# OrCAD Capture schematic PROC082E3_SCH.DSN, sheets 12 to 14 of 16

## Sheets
12 16. HARDWARE SCHEMATICS: title: HARDWARE SCHEMATICS
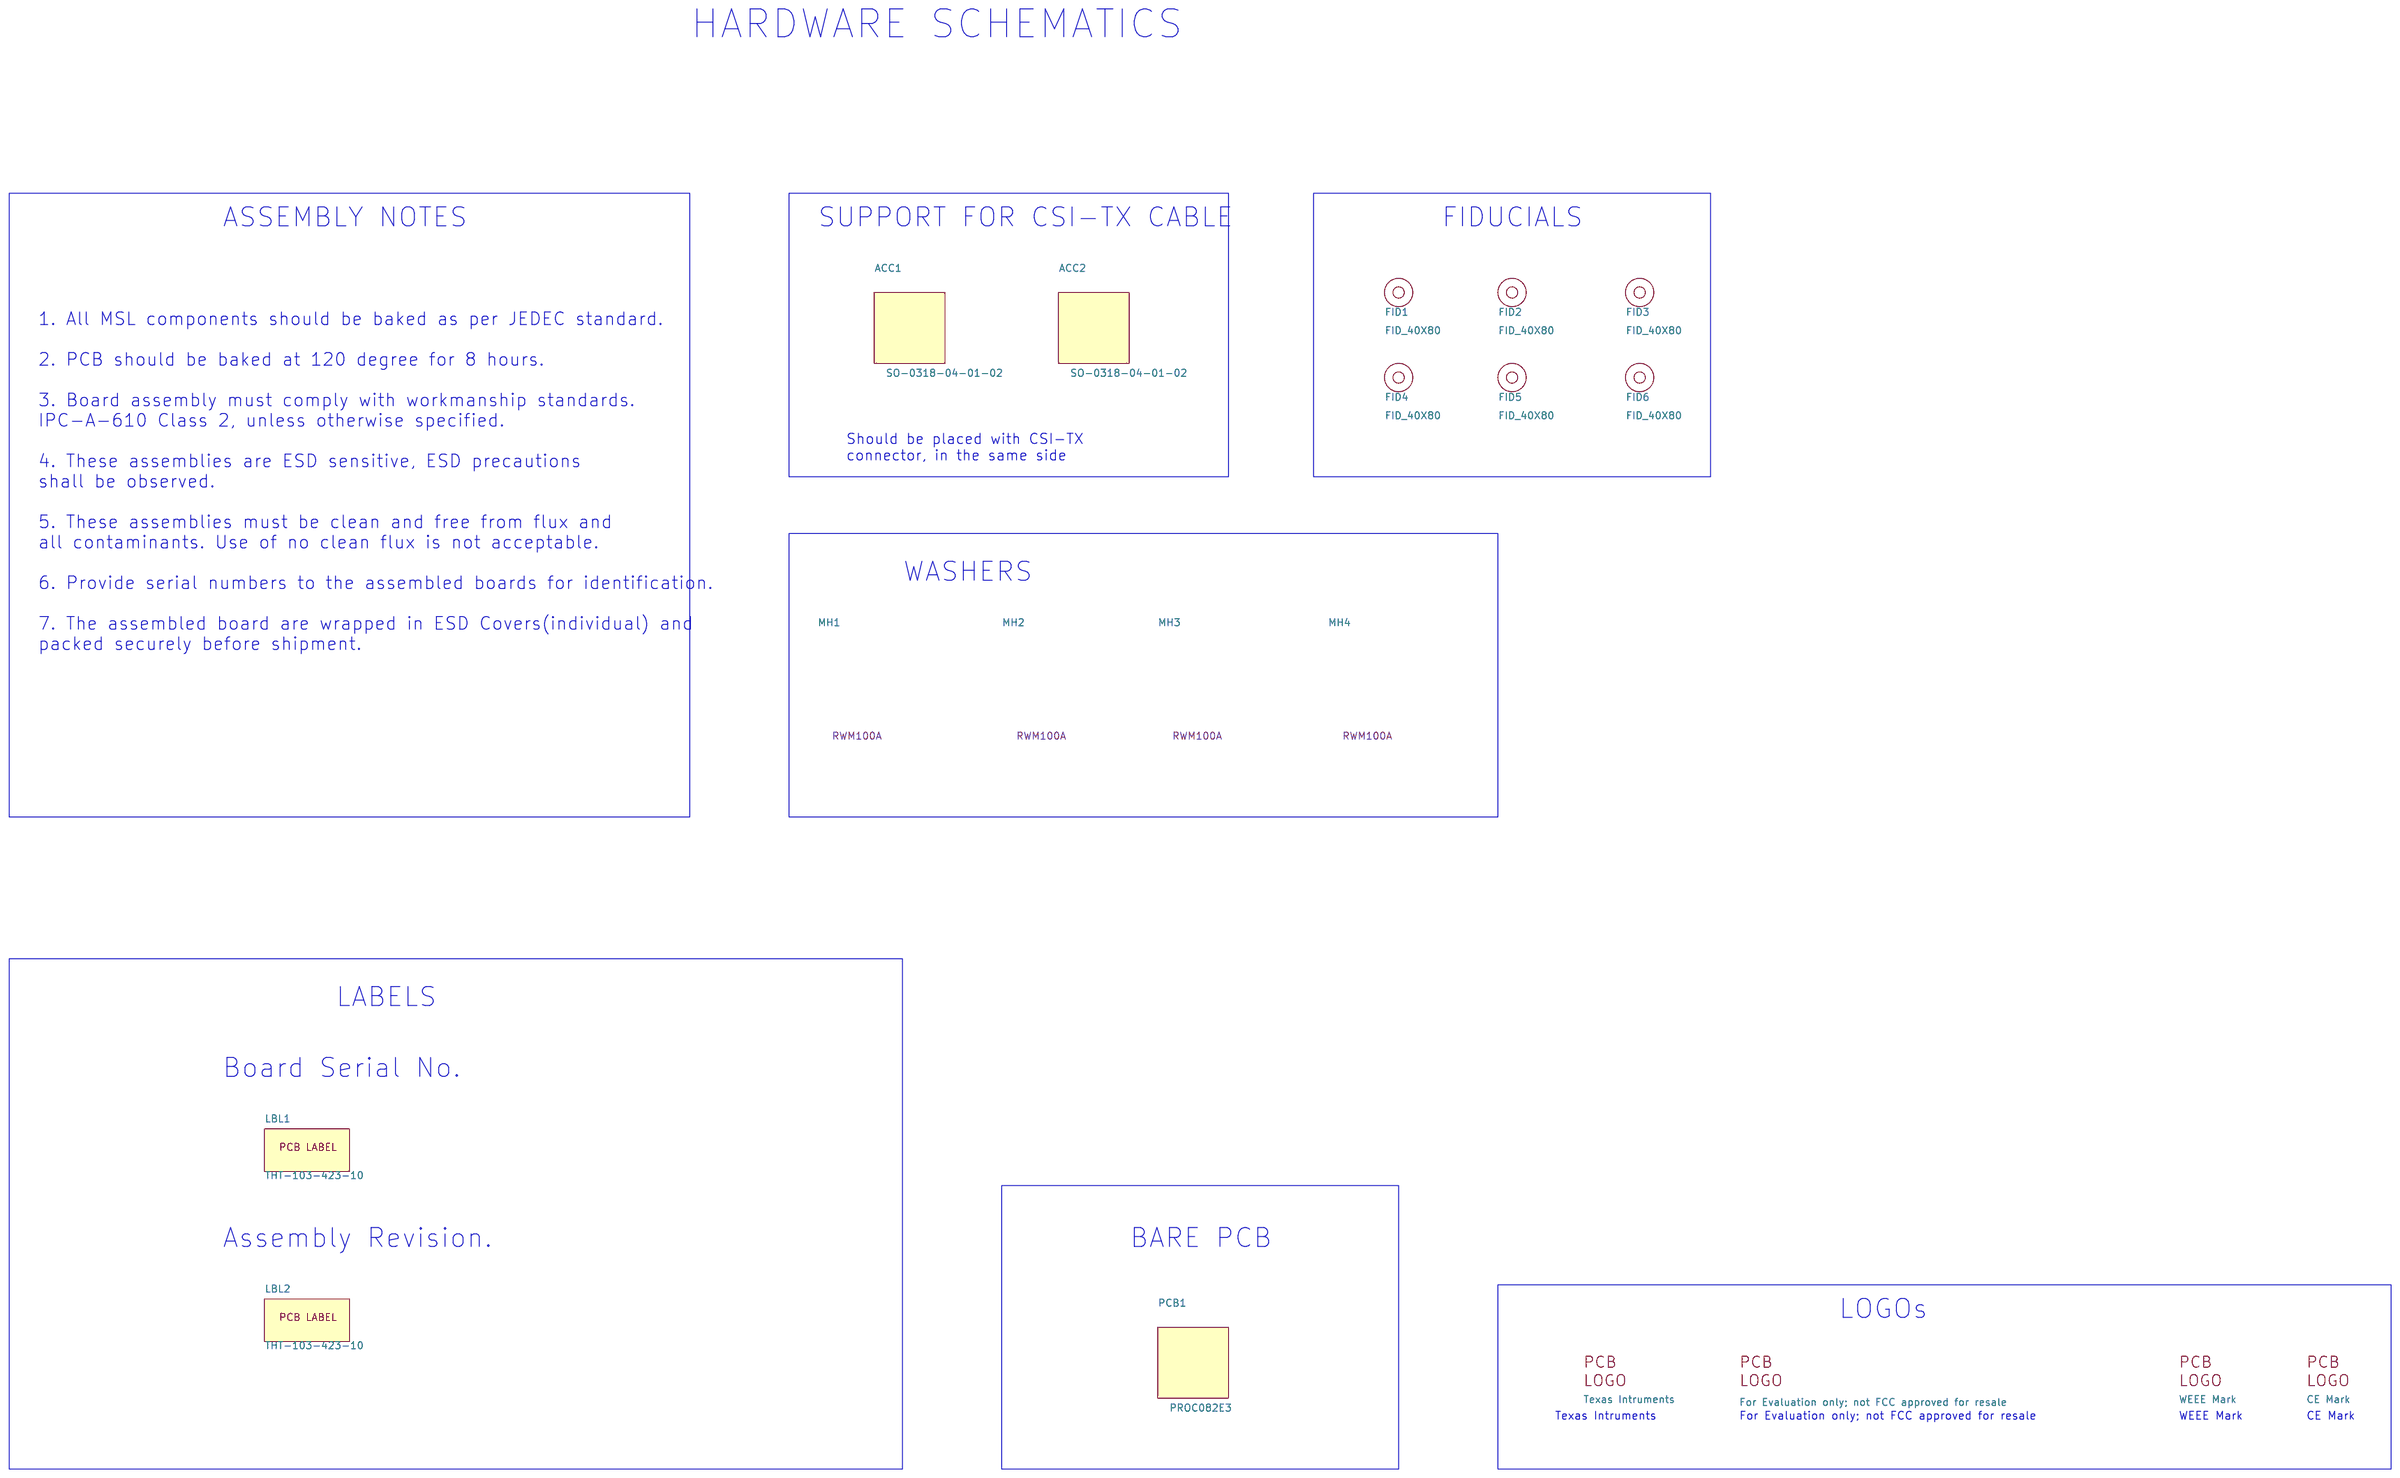
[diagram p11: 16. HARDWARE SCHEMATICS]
13 08. FPD LINK_CAM/RDR_IN1: size C; title: FPD Link Camera/RADAR Input1
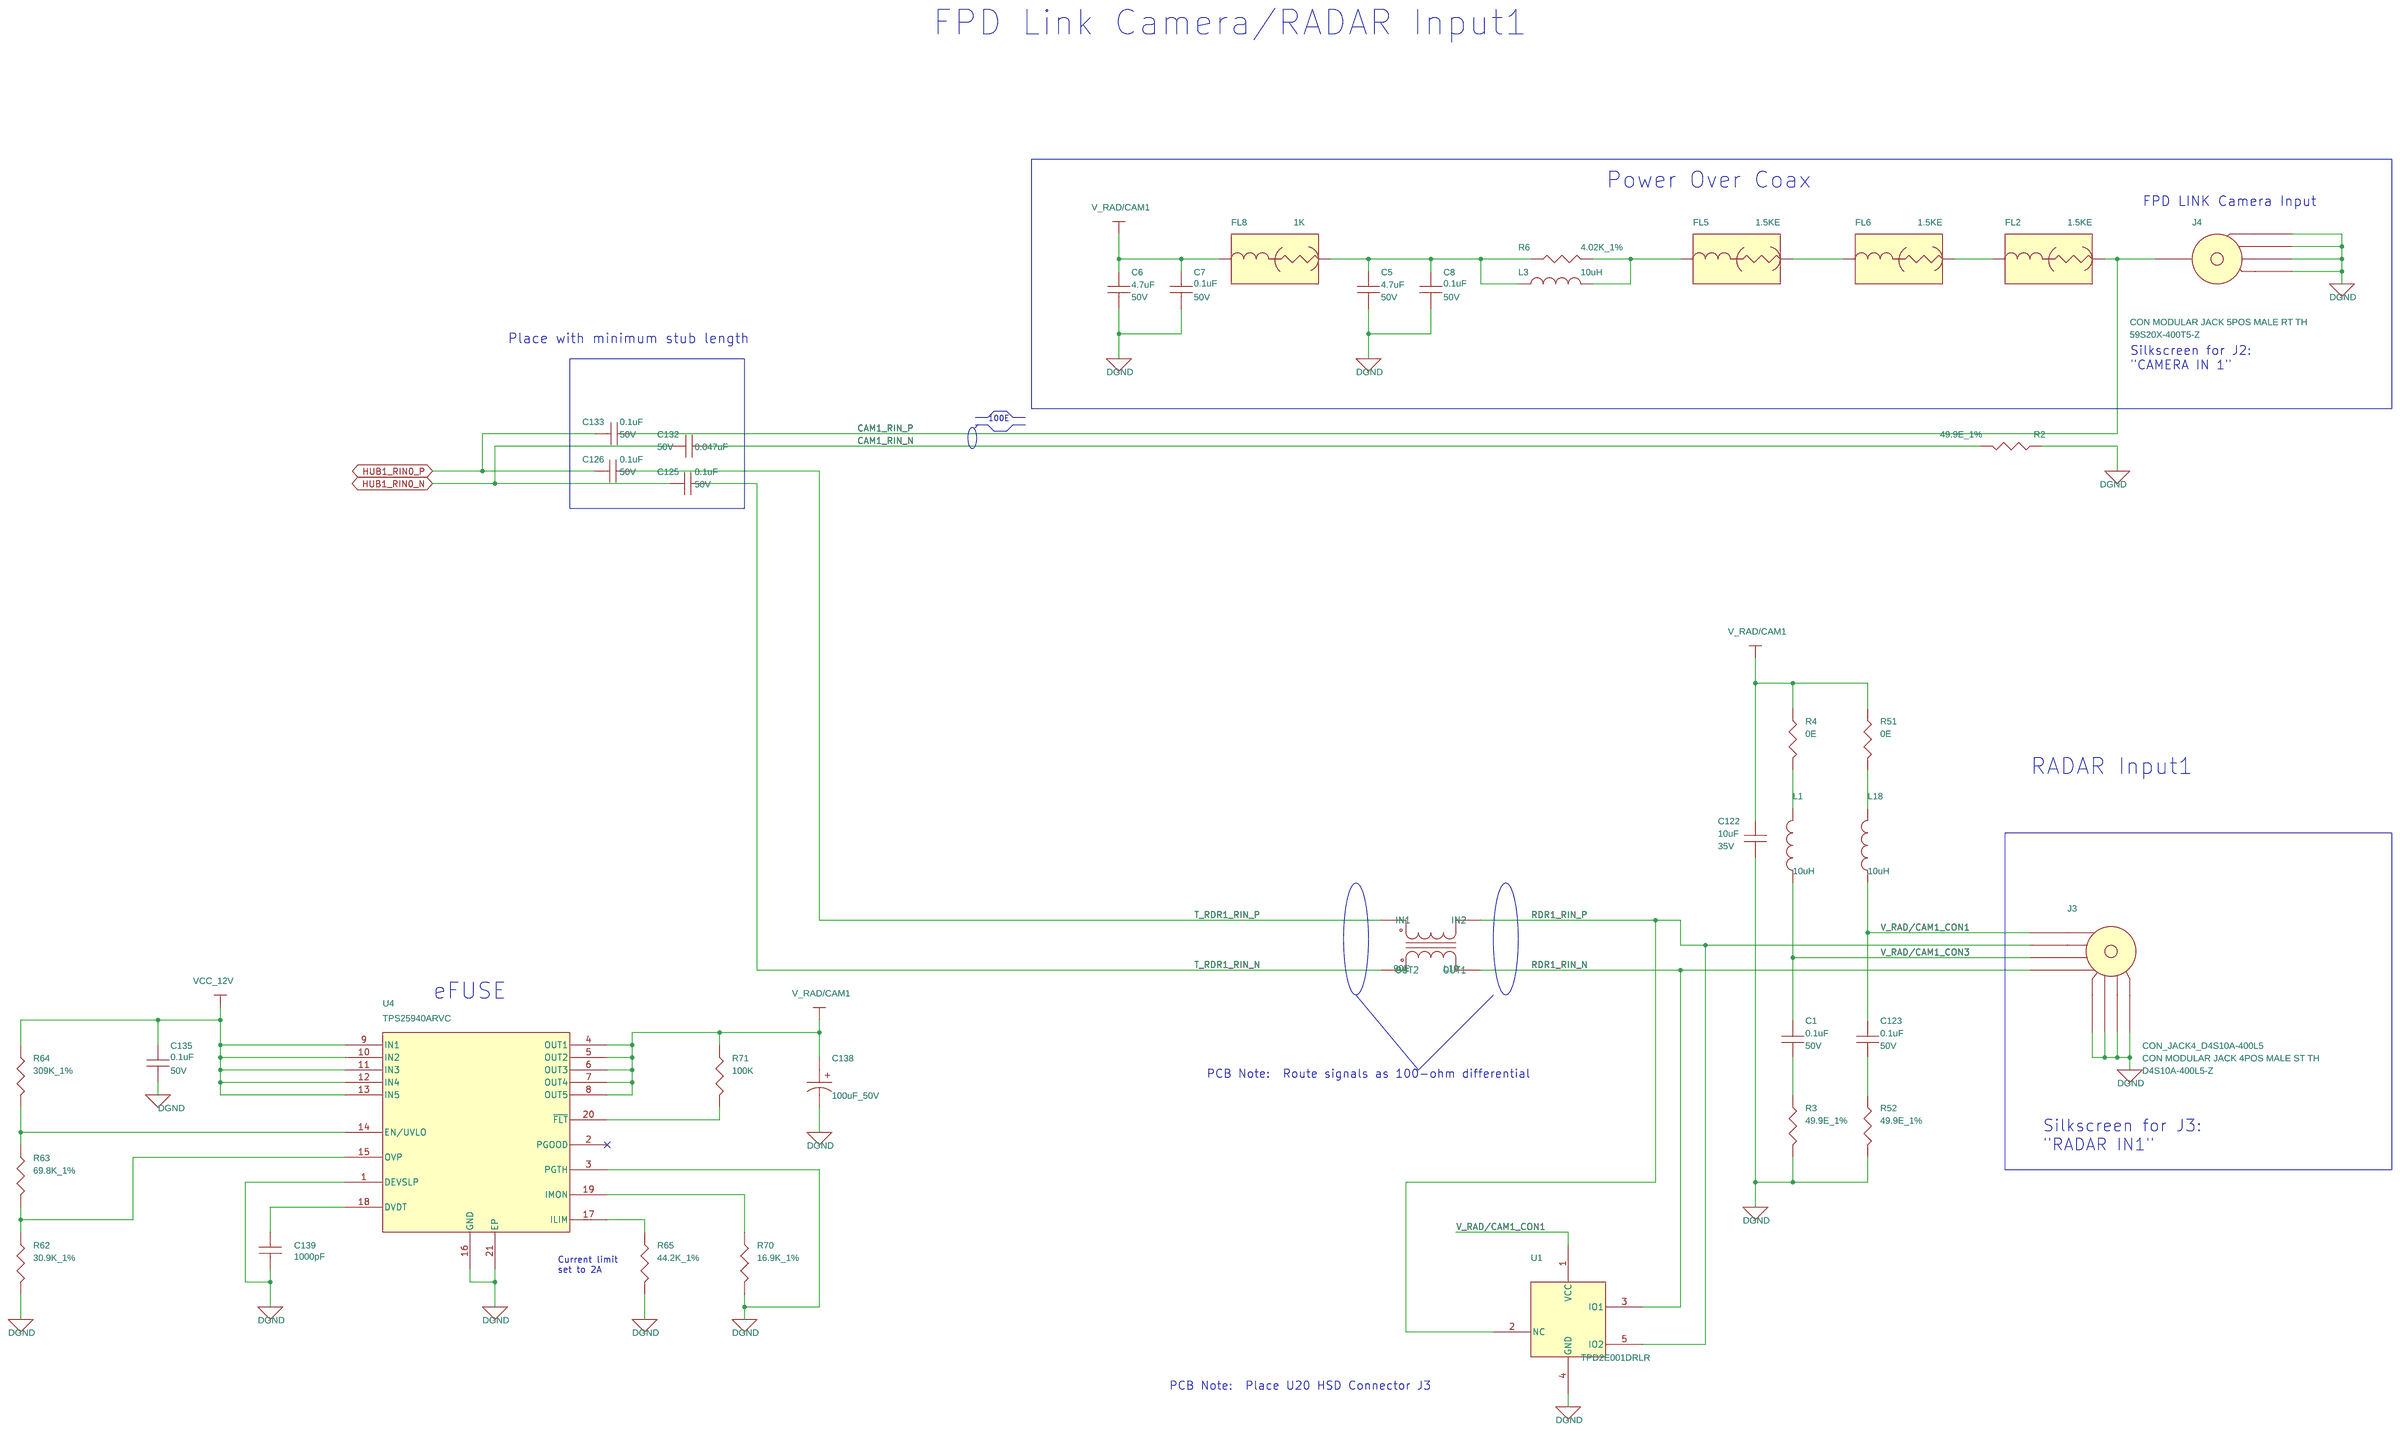
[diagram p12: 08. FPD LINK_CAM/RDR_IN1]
14 10. FPD LINK_CAM/RDR_IN3: size C; title: FPD Link Camera/RADAR Input3
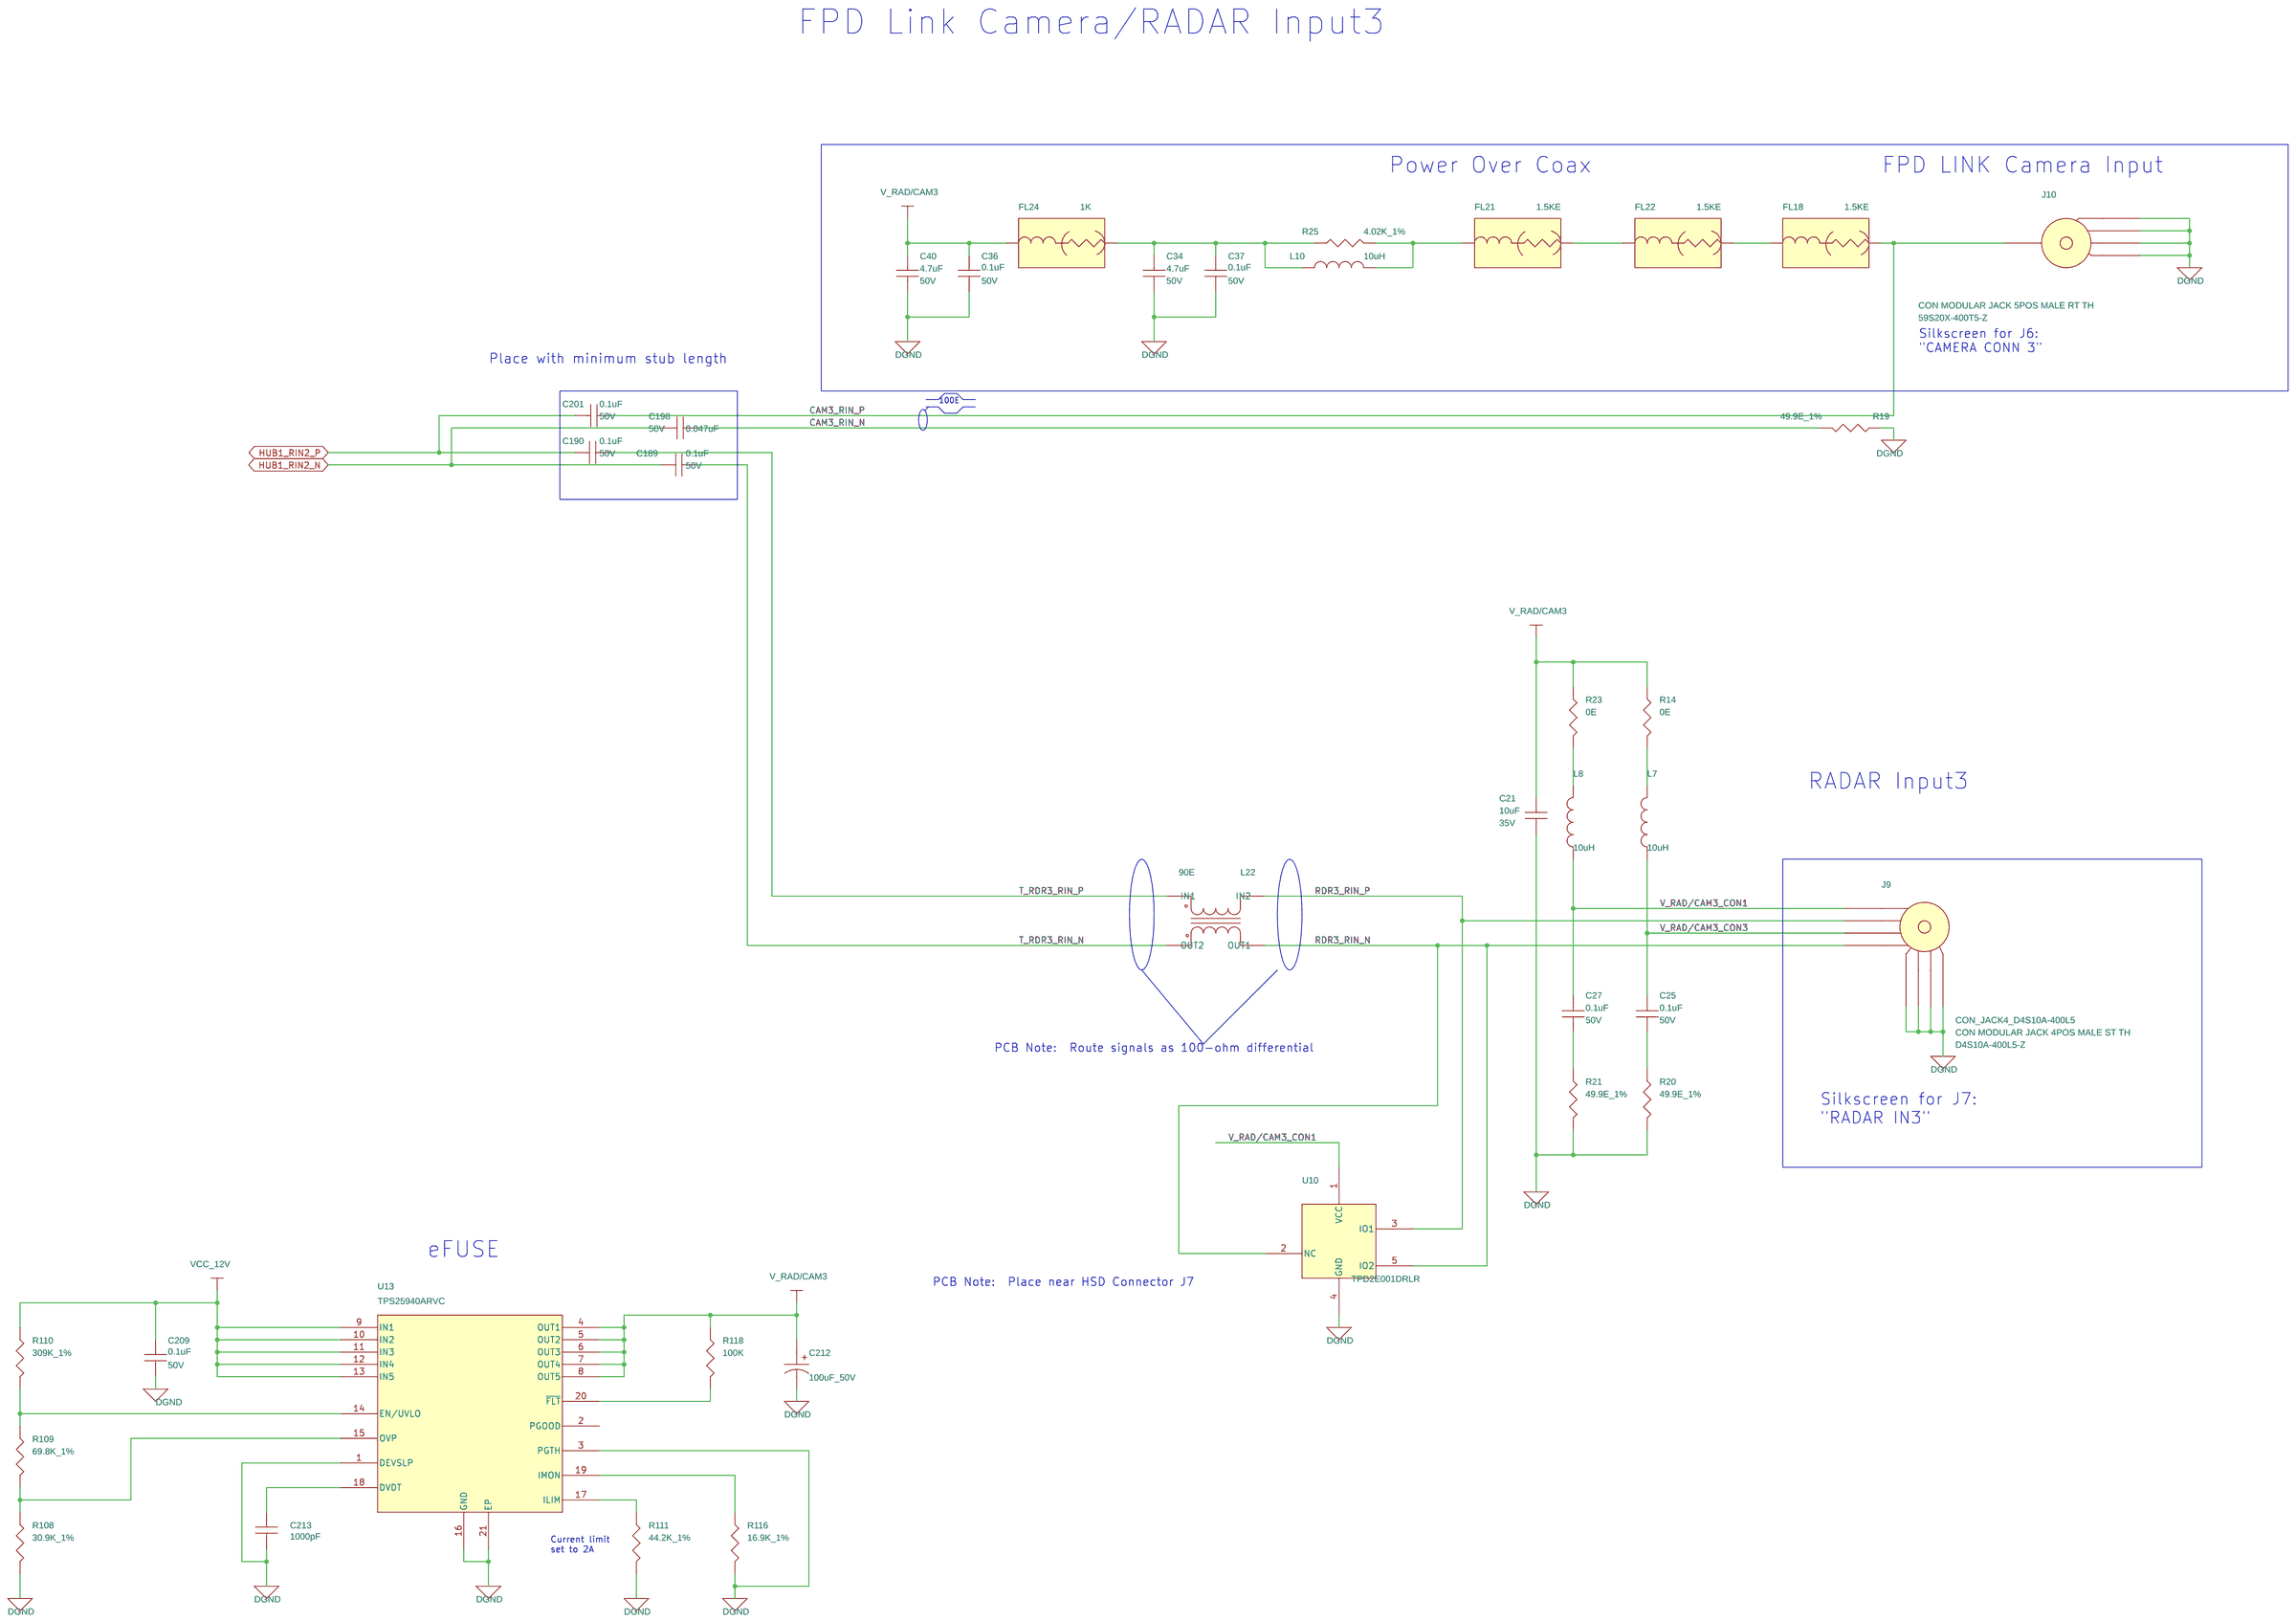
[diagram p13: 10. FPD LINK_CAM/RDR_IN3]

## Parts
sheet 08. FPD LINK_CAM/RDR_IN1
C1  0.1uF  [CAP0402_0-75]
C5  4.7uF  [CAP1206_2]
C6  4.7uF  [CAP1206_2]
C7  0.1uF  [CAP0402_0-75]
C8  0.1uF  [CAP0402_0-75]
C122  10uF  [CAP1206_1]
C123  0.1uF  [CAP0402_0-75]
C125  0.1uF  [CAP0402_0-75]
C126  0.1uF  [CAP0402_0-75]
C132  0.047uF  [CAP0402_0-75]
C133  0.1uF  [CAP0402_0-75]
C135  0.1uF  [CAP0402_0-75]
C138  100uF_50V  [CAPAE_D8CASE_8]
C139  1000pF  [CAP0402_0-75]
FL2  1.5KE  [EMIFIL_BLM18R_0603]
FL5  1.5KE  [EMIFIL_BLM18R_0603]
FL6  1.5KE  [EMIFIL_BLM18R_0603]
FL8  1K  [EMIFIL_BLM18A_0603_1]
J3  CON_JACK4_D4S10A-400L5  [CON_JACK4_D4S10A-400L5-Z_P_S_T_15-4]
J4  CON_JACK5_59S20X-400T5  [CON_JACK5_59S20X-400T5-Z_P_R_T_10-1]
L1  10uH  [IND_MLZ2012N_90X60_SMD]
L3  10uH  [IND_MLZ2012N_90X60_SMD]
L18  10uH  [IND_MLZ2012N_90X60_SMD]
L19  90E  [IND4_DLW21H_90X60_SMD_1-4]
R2  49.9E_1%  [RES0402_0-5]
R3  49.9E_1%  [RES0402_0-5]
R4  0E  [RES0603_0-5]
R6  4.02K_1%  [RES0603_0-5]
R51  0E  [RES0603_0-5]
R52  49.9E_1%  [RES0402_0-5]
R62  30.9K_1%  [RES0402_0-5]
R63  69.8K_1%  [RES0402_0-5]
R64  309K_1%  [RES0402_0-5]
R65  44.2K_1%  [RES0402_0-5]
R70  16.9K_1%  [RES0402_0-5]
R71  100K  [RES0402_0-5]
U1  TPD2E001DRLR  [SOT553-5_0-6]
U4  TPS25940ARVC  [QFN20_19-68_120X160_0-8]
sheet 10. FPD LINK_CAM/RDR_IN3
C21  10uF  [CAP1206_1]
C25  0.1uF  [CAP0402_0-75]
C27  0.1uF  [CAP0402_0-75]
C34  4.7uF  [CAP1206_2]
C36  0.1uF  [CAP0402_0-75]
C37  0.1uF  [CAP0402_0-75]
C40  4.7uF  [CAP1206_2]
C189  0.1uF  [CAP0402_0-75]
C190  0.1uF  [CAP0402_0-75]
C198  0.047uF  [CAP0402_0-75]
C201  0.1uF  [CAP0402_0-75]
C209  0.1uF  [CAP0402_0-75]
C212  100uF_50V  [CAPAE_D8CASE_8]
C213  1000pF  [CAP0402_0-75]
FL18  1.5KE  [EMIFIL_BLM18R_0603]
FL21  1.5KE  [EMIFIL_BLM18R_0603]
FL22  1.5KE  [EMIFIL_BLM18R_0603]
FL24  1K  [EMIFIL_BLM18A_0603_1]
J9  CON_JACK4_D4S10A-400L5  [CON_JACK4_D4S10A-400L5-Z_P_S_T_15-4]
J10  CON_JACK5_59S20X-400T5  [CON_JACK5_59S20X-400T5-Z_P_R_T_10-1]
L7  10uH  [IND_MLZ2012N_90X60_SMD]
L8  10uH  [IND_MLZ2012N_90X60_SMD]
L10  10uH  [IND_MLZ2012N_90X60_SMD]
L22  90E  [IND4_DLW21H_90X60_SMD_1-4]
R14  0E  [RES0603_0-5]
R19  49.9E_1%  [RES0402_0-5]
R20  49.9E_1%  [RES0402_0-5]
R21  49.9E_1%  [RES0402_0-5]
R23  0E  [RES0603_0-5]
R25  4.02K_1%  [RES0603_0-5]
R108  30.9K_1%  [RES0402_0-5]
R109  69.8K_1%  [RES0402_0-5]
R110  309K_1%  [RES0402_0-5]
R111  44.2K_1%  [RES0402_0-5]
R116  16.9K_1%  [RES0402_0-5]
R118  100K  [RES0402_0-5]
U10  TPD2E001DRLR  [SOT553-5_0-6]
U13  TPS25940ARVC  [QFN20_19-68_120X160_0-8]
sheet 16. HARDWARE SCHEMATICS
ACC1  SO-0318-04-01-02  [ACC_SO-0318-04-01_TH_3-3]
ACC2  SO-0318-04-01-02  [ACC_SO-0318-04-01_TH_3-3]
FID1  FID_40X80  [FID_40X80]
FID2  FID_40X80  [FID_40X80]
FID3  FID_40X80  [FID_40X80]
FID4  FID_40X80  [FID_40X80]
FID5  FID_40X80  [FID_40X80]
FID6  FID_40X80  [FID_40X80]
LBL1  THT-103-423-10  [NA]
LBL2  THT-103-423-10  [NA]
LOGO1  Texas Intruments  [TI_Stacked_Overlay_Small]
LOGO2  For Evaluation only; not FCC approved for resale  [FCC_disclaimer]
LOGO3  WEEE Mark  [TI_Stacked_Overlay_Small]
LOGO4  CE Mark  [TI_Stacked_Overlay_Small]
MH1  FLAT WASHER_M3  [NA]
MH2  FLAT WASHER_M3  [NA]
MH3  FLAT WASHER_M3  [NA]
MH4  FLAT WASHER_M3  [NA]
PCB1  PROC082E3

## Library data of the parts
C1 C7 C8 C25 C27 C36 C37 C123 C125 C126 C133 C135 C189 C190 C201 C209 = CAP: CAP CERAMIC 0.1uF 50V 10% X7R 0402; Chkd/date: MANIRAJA/131217; Crtd /date: ALVY/131217; Custom_Duty: 15%; Customs_HS_Code: 85322990; Distributor_name: DIGIKEY; Distributor_part_number: 478-10043-1-ND; Footprint Path: Y:\MIS_DATABASE\Library\ALTIUM_TOOL\PCB_FOOTPRINTS\Altium_Footprint_Lib.PcbLib; Height: 0.56MM; Library Path: Y:\MIS_DATABASE\Library\ALTIUM_TOOL\SCHEMATICS_PARTS\MS_DISCRETE_Library.schlib; Mfr_name: AVX CORPORATION; Mfr_part_number: 04025C104KAT2A; Mistral Part No: 120011100014-R; Package: 0402; Part_type: CAPACITORS\CERAMIC; Project: ASL_LIU_TYPE-II; RoHS: RoHS; Temperature: -55°C+125°C; Tolerance: 10%; Voltage: 50V; Wattage: NA; Weight: 0.65mg; Datasheet: Y:\MIS_DATABASE\DATASHEETS\CAPACITORS\AVX_MLC.PDF
C5 C6 C34 C40 = CAP: CAP CERAMIC 4.7uF 50V 10% X7R 1206; Chkd/date: VASANTHA/100315; Crtd /date: NAVEED/240714; Custom_Duty: 15%; Customs_HS_Code: 85322990; Distributor_name: DIGIKEY; Distributor_part_number: 587-2994-1-ND; Footprint Path: Y:\MIS_DATABASE\Library\ALTIUM_TOOL\PCB_FOOTPRINTS\Altium_Footprint_Lib.PcbLib; Height: 1.80MM; Library Path: Y:\MIS_DATABASE\Library\ALTIUM_TOOL\SCHEMATICS_PARTS\MS_DISCRETE_Library.schlib; Mfr_name: TAIYO YUDEN; Mfr_part_number: UMK316AB7475KL-T; Mistral Part No: 120014070019-R; Package: 1206; Part_type: CAPACITORS\CERAMIC; Project: MS_ADE_PSM_PSU; RoHS: RoHS; Temperature: -55°C+125°C; Tolerance: 10%; Voltage: 50V; Wattage: NA; Weight: 16.2mg; Datasheet: Y:\MIS_DATABASE\DATASHEETS\CAPACITORS\UMK316AB7475KL-T.PDF
C21 C122 = CAP: CAP CERAMIC 10uF 35V 10% X5R 1206; Chkd/date: MANIRAJA/130618; Crtd /date: MANIRAJA/130618; Custom_Duty: 15%; Customs_HS_Code: 85322990; Distributor_name: DIGIKEY; Distributor_part_number: 490-9964-1-ND; Footprint Path: Y:\MIS_DATABASE\Library\ALTIUM_TOOL\PCB_FOOTPRINTS\Altium_Footprint_Lib.PcbLib; Height: 0.95MM; Library Path: Y:\MIS_DATABASE\Library\ALTIUM_TOOL\SCHEMATICS_PARTS\MS_DISCRETE_Library.schlib; Mfr_name: MURATA; Mfr_part_number: GRM319R6YA106KA12D; Mistral Part No: 120018060022-R; Package: 1206; Part_type: CAPACITORS\CERAMIC; Project: MYTHIC_PCIE_DB; RoHS: RoHS; Temperature: -55°C+85°C; Tolerance: 10%; Voltage: 35V; Wattage: NA; Weight: 40mg; Datasheet: Y:\MIS_DATABASE\DATASHEETS\CAPACITORS\GRM319R6YA106KA12D.PDF
C132 C198 = CAP: CAP CERAMIC 0.047uF 50V 10% X7R 0402; Chkd/date: MANIRAJA/240118; Crtd /date: MANIRAJA/240118; Custom_Duty: 15%; Customs_HS_Code: 85322990; Distributor_name: DIGIKEY; Distributor_part_number: GRM155R71H473KE14J-ND; Footprint Path: Y:\MIS_DATABASE\Library\ALTIUM_TOOL\PCB_FOOTPRINTS\Altium_Footprint_Lib.PcbLib; Height: 0.55MM; Library Path: Y:\MIS_DATABASE\Library\ALTIUM_TOOL\SCHEMATICS_PARTS\MS_DISCRETE_Library.schlib; Mfr_name: MURATA; Mfr_part_number: GRM155R71H473KE14J; Mistral Part No: 120018010011-R; Package: 0402; Part_type: CAPACITORS\CERAMIC; Project: TI_MAXIE_CPB; RoHS: RoHS; Temperature: -55°C+125°C; Tolerance: 10%; Voltage: 50V; Wattage: NA; Weight: 6mg; Datasheet: Y:\MIS_DATABASE\DATASHEETS\CAPACITORS\GRM155R71H473KE14.PDF
C138 C212 = CAP_POL: CAP ELECTROLYTIC 100uF 50V 20% D8CASE_6666; Chkd/date: MANIRAJA/051018; Crtd /date: ALVY/051018; Custom_Duty: 15%; Customs_HS_Code: 85322990; Distributor_name: DIGIKEY; Distributor_part_number: PCE5024CT-ND; Footprint Path: Y:\MIS_DATABASE\Library\ALTIUM_TOOL\PCB_FOOTPRINTS\Altium_Footprint_Lib.PcbLib; Height: 8.00MM; Library Path: Y:\MIS_DATABASE\Library\ALTIUM_TOOL\SCHEMATICS_PARTS\MS_DISCRETE_Library.schlib; Mfr_name: PANASONIC-ECG; Mfr_part_number: EEE-FTH101XAP; Mistral Part No: 120018100013-R; Package: D8CASE_6666; Part_type: CAPACITORS\ELECTROLYTIC; Project: TI_J7_SVB-DUT; RoHS: RoHS; Temperature: -55°C+105°C; Tolerance: 20%; Voltage: 50V; Wattage: NA; Weight: 440mg; Datasheet: Y:\MIS_DATABASE\DATASHEETS\CAPACITORS\FTV-SER.PDF
C139 C213 = CAP: CAP CERAMIC 1000pF 50V 5% C0G(NP0) 0402; Chkd/date: VASANTHA/281216; Crtd /date: MAZHAR/290806; Custom_Duty: 15%; Customs_HS_Code: 85322990; Distributor_name: DIGIKEY; Distributor_part_number: 490-3244-1-ND; Footprint Path: Y:\MIS_DATABASE\Library\ALTIUM_TOOL\PCB_FOOTPRINTS\Altium_Footprint_Lib.PcbLib; Height: 0.55MM; Library Path: Y:\MIS_DATABASE\Library\ALTIUM_TOOL\SCHEMATICS_PARTS\MS_DISCRETE_Library.schlib; Mfr_name: MURATA; Mfr_part_number: GRM1555C1H102JA01D; Mistral Part No: 120016110009-R; Package: 0402; Part_type: CAPACITORS\CERAMIC; Project: SVDO_RMB_MMA; RoHS: RoHS; Temperature: -55°C+125°C; Tolerance: 5%; Voltage: 50V; Wattage: NA; Weight: 6mg; Datasheet: Y:\MIS_DATABASE\DATASHEETS\CAPACITORS\MURATA-GXX-SER_NOV17.PDF
FL2 FL5 FL6 FL18 FL21 FL22 = EMIFILTER_IND: FERRITE BEAD 1.5KE 500MA 0603; Chkd/date: RAGESH/111010; Crtd /date: MUDDU/050210; Custom_Duty: 24%; Customs_HS_Code: 85437099; Distributor_name: DIGIKEY; Distributor_part_number: 490-5216-1-ND; Footprint Path: Y:\MIS_DATABASE\Library\ALTIUM_TOOL\PCB_FOOTPRINTS\Altium_Footprint_Lib.PcbLib; Height: 0.95MM; Library Path: Y:\MIS_DATABASE\Library\ALTIUM_TOOL\SCHEMATICS_PARTS\MS_FILTER_Library.schlib; Mfr_name: MURATA; Mfr_part_number: BLM18HE152SN1; Mistral Part No: 130010020011; Package: 0603; Part_type: FILTER; Project: NPOL_CONTROLLERCARD; Temperature: -55°C+125°C; Tolerance: NA; Voltage: NA; Wattage: NA; Weight: NA; Datasheet: Y:\MIS_DATABASE\DATASHEETS\DISCRETES\INDUCTORS\BLM18H.PDF
FL8 FL24 = EMIFILTER_IND: IND FERRITE BEAD CHIP 1K 450mA 0603; Chkd/date: MANIRAJA/070818; Crtd /date: USMAN/070409; Custom_Duty: 24%; Customs_HS_Code: 85437099; Distributor_name: DIGIKEY; Distributor_part_number: 490-1015-1-ND; Footprint Path: Y:\MIS_DATABASE\Library\ALTIUM_TOOL\PCB_FOOTPRINTS\Altium_Footprint_Lib.PcbLib; Height: 0.95MM; Library Path: Y:\MIS_DATABASE\Library\ALTIUM_TOOL\SCHEMATICS_PARTS\MS_DISCRETE_Library.schlib; Mfr_name: MURATA; Mfr_part_number: BLM18AG102SN1D; Mistral Part No: 130009070006-R; Package: 0603; Part_type: INDUCTOR; Project: AARDK; RoHS: RoHS; Temperature: -55°C+125°C; Tolerance: 25%; Voltage: NA; Wattage: NA; Weight: 5mg; Datasheet: Y:\MIS_DATABASE\DATASHEETS\DISCRETES\INDUCTORS\BLM18A-N1.PDF
J3 J9 = CON_JACK4_EXG.0B.304: CON MODULAR JACK 4POS MALE ST TH; Chkd/date: MANIRAJA/251018; Crtd /date: ALVY/251018; Custom_Duty: 24%; Customs_HS_Code: 85369090; Distributor_name: DIGIKEY; Distributor_part_number: D4S10A-400L5-Z-ND; Footprint Path: Y:\MIS_DATABASE\Library\ALTIUM_TOOL\PCB_FOOTPRINTS\Altium_Footprint_Lib.PcbLib; Height: 15.40MM; Library Path: Y:\MIS_DATABASE\Library\ALTIUM_TOOL\SCHEMATICS_PARTS\MS_CONNECTOR_Library.schlib; Mfr_name: ROSENBERGER; Mfr_part_number: D4S10A-400L5-Z; Mistral Part No: 150018100044-R; Package: THRU-HOLE; Part_type: CONNECTOR\JACK; Project: TI_J7ES_EVM_FUSION2_SER_CAP; RoHS: RoHS; Temperature: -40°C+105°C; Tolerance: NA; Voltage: NA; Wattage: NA; Weight: 2900mg; Datasheet: Y:\MIS_DATABASE\DATASHEETS\CONNECTORS\D4S10A-400L5-Y.PDF
J4 J10 = CON5_MCXJACK_TH: CON MODULAR JACK 5POS MALE RT TH; Chkd/date: MANIRAJA/020519; Crtd /date: MANIRAJA/020519; Custom_Duty: 24%; Customs_HS_Code: 85369090; Distributor_name: NA; Distributor_part_number: NA; Footprint Path: Y:\MIS_DATABASE\Library\ALTIUM_TOOL\PCB_FOOTPRINTS\Altium_Footprint_Lib.PcbLib; Height: 10.05MM; Library Path: Y:\MIS_DATABASE\Library\ALTIUM_TOOL\SCHEMATICS_PARTS\MS_CONNECTOR_Library.schlib; Mfr_name: ROSENBERGER; Mfr_part_number: 59S20X-400T5-Z; Mistral Part No: 150019050002-R; Package: THRU-HOLE; Part_type: CONNECTOR\JACK; Project: TI_J7ES_EVM_FUSION2_SER_CAP; RoHS: RoHS; Temperature: -40°C+105°C; Tolerance: NA; Voltage: NA; Wattage: NA; Weight: 3880mg; Datasheet: Y:\MIS_DATABASE\DATASHEETS\CONNECTORS\59S20X-400T5-Y.PDF
L1 L3 L7 L8 L10 L18 = INDUCTOR: IND 10uH 20% 500mA SMD; Alternate_mfr_name_A: TDK CORPORATION; Alternate_mfr_part_number_A: MLZ2012N100LT000; Chkd/date: BALACHANDAR/150514; Crtd /date: SARANYA/120514; Custom_Duty: 24%; Customs_HS_Code: 85437099; Distributor_name: MOUSER; Distributor_name_A: DIGIKEY; Distributor_part_number: 810-MLZ2012N100L; Distributor_part_number_A: 445-6762-1-ND; Height: 1.25MM; Mfr_name: TDK CORPORATION; Mfr_part_number: MLZ2012N100L; Mistral Part No: 130014050064-R; Package: 0805; Project: AEGIS GP BETA2; RoHS: RoHS; Temperature: -55°C+125°C; Tolerance: NA; Voltage: NA; Wattage: NA; Weight: 14mg; Datasheet: Y:\MIS_DATABASE\DATASHEETS\DISCRETES\INDUCTORS\MLZ2012_SERIES.PDF
L19 L22 = INDUCTOR_DLW31S: IND COMMON MODE CHOKE 90E 280mA SMD; Chkd/date: MANIRAJA/270619; Crtd /date: MANIRAJA/270619; Custom_Duty: 24%; Customs_HS_Code: 85437099; Distributor_name: NA; Distributor_part_number: NA; Footprint Path: Y:\MIS_DATABASE\Library\ALTIUM_TOOL\PCB_FOOTPRINTS\Altium_Footprint_Lib.PcbLib; Height: 1.40MM; Library Path: Y:\MIS_DATABASE\Library\ALTIUM_TOOL\SCHEMATICS_PARTS\MS_DISCRETE_Library.schlib; Mfr_name: MURATA; Mfr_part_number: DLW21SZ900HQ2B; Mistral Part No: 130019060035-R; Package: SMD; Part_type: INDUCTOR; Project: TI_J7ES_CP; RoHS: RoHS; Temperature: -40°C+105°C; Tolerance: NA; Voltage: NA; Wattage: NA; Weight: 11mg; Datasheet: Y:\MIS_DATABASE\DATASHEETS\DISCRETES\INDUCTORS\DLW21SZ900HQ2B.PDF
R2 R3 R19-R21 R52 = RESISTOR: RES 49.9E 1/10W 1% 0402; Chkd/date: VASANTHA/201216; Crtd /date: MAZHAR/201005; Custom_Duty: 15%; Customs_HS_Code: 85332119; Distributor_name: DIGIKEY; Distributor_part_number: P49.9LCT-ND; Footprint Path: Y:\MIS_DATABASE\Library\ALTIUM_TOOL\PCB_FOOTPRINTS\Altium_Footprint_Lib.PcbLib; Height: 0.40MM; Library Path: Y:\MIS_DATABASE\Library\ALTIUM_TOOL\SCHEMATICS_PARTS\MS_DISCRETE_Library.schlib; Mfr_name: PANASONIC-ECG; Mfr_part_number: ERJ-2RKF49R9X; Mistral Part No: 110009030897-R; Package: 0402; Part_type: RESISTORS\FIXED; Project: RED EYE; RoHS: RoHS; Temperature: -55°C+155°C; Tolerance: 1%; Voltage: NA; Wattage: 1/10W; Weight: 0.8mg; Datasheet: Y:\MIS_DATABASE\DATASHEETS\RESISTORS\PAN-ERJSER_NOV17.PDF
R4 R14 R23 R51 = RESISTOR: RES 0E 1/10W JUMPER 0603; Chkd/date: MANIRAJA/220618; Crtd /date: MUDDU/120310; Custom_Duty: 15%; Customs_HS_Code: 85332119; Distributor_name: DIGIKEY; Distributor_part_number: 541-2968-1-ND; Footprint Path: Y:\MIS_DATABASE\Library\ALTIUM_TOOL\PCB_FOOTPRINTS\Altium_Footprint_Lib.PcbLib; Height: 0.50MM; Library Path: Y:\MIS_DATABASE\Library\ALTIUM_TOOL\SCHEMATICS_PARTS\MS_DISCRETE_Library.schlib; Mfr_name: VISHAY; Mfr_part_number: CRCW06030000Z0EB; Mistral Part No: 110010030044-R; Package: 0603; Part_type: RESISTORS\FIXED; Project: BLR-3 PSPU; RoHS: RoHS; Temperature: -55°C+155°C; Tolerance: NA; Voltage: NA; Wattage: 1/10W; Weight: 2mg; Datasheet: Y:\MIS_DATABASE\DATASHEETS\RESISTORS\CRCW0603.PDF
R6 R25 = RESISTOR: RES 4.02K 1/10W 1% 0603; Chkd/date: VASANTHA/201216; Crtd /date: MAZHAR/241109; Custom_Duty: 15%; Customs_HS_Code: 85332119; Distributor_name: DIGIKEY; Distributor_part_number: 541-4.02KHCT-ND; Footprint Path: Y:\MIS_DATABASE\Library\ALTIUM_TOOL\PCB_FOOTPRINTS\Altium_Footprint_Lib.PcbLib; Height: 0.50MM; Library Path: Y:\MIS_DATABASE\Library\ALTIUM_TOOL\SCHEMATICS_PARTS\MS_DISCRETE_Library.schlib; Mfr_name: VISHAY; Mfr_part_number: CRCW06034K02FKEA; Mistral Part No: 110009110009-R; Package: 0603; Part_type: RESISTORS\FIXED; Project: NPOL_FPS; RoHS: RoHS; Temperature: -55°C+155°C; Tolerance: 1%; Voltage: NA; Wattage: 1/10W; Weight: 2mg; Datasheet: Y:\MIS_DATABASE\DATASHEETS\RESISTORS\CRCW0603.PDF
R62 R108 = RESISTOR: RES 30.9K 1/10W 1% 0402; Chkd/date: MAZHAR/080311; Crtd /date: BAVISH/230211; Custom_Duty: 15%; Customs_HS_Code: 85332119; Distributor_name: DIGIKEY; Distributor_part_number: P30.9KLCT-ND; Footprint Path: Y:\MIS_DATABASE\Library\ALTIUM_TOOL\PCB_FOOTPRINTS\Altium_Footprint_Lib.PcbLib; Height: 0.40MM; Library Path: Y:\MIS_DATABASE\Library\ALTIUM_TOOL\SCHEMATICS_PARTS\MS_DISCRETE_Library.schlib; Mfr_name: PANASONIC-ECG; Mfr_part_number: ERJ-2RKF3092X; Mistral Part No: 110011020022-R; Package: 0402; Part_type: RESISTORS\FIXED; Project: GOLDEN-I; RoHS: RoHS; Temperature: -55°C+155°C; Tolerance: 1%; Voltage: NA; Wattage: 1/10W; Weight: 0.8mg; Datasheet: Y:\MIS_DATABASE\DATASHEETS\RESISTORS\PAN-ERJSER_NOV17.PDF
R63 R109 = RESISTOR: RES 69.8K 1/10W 1% 0402; Chkd/date: SHREESHAIL/121205; Crtd /date: MAZHAR/030605; Custom_Duty: 15%; Customs_HS_Code: 85332119; Distributor_name: DIGIKEY; Distributor_part_number: P69.8KLCT-ND; Footprint Path: Y:\MIS_DATABASE\Library\ALTIUM_TOOL\PCB_FOOTPRINTS\Altium_Footprint_Lib.PcbLib; Height: 0.40MM; Library Path: Y:\MIS_DATABASE\Library\ALTIUM_TOOL\SCHEMATICS_PARTS\MS_DISCRETE_Library.schlib; Mfr_name: PANASONIC-ECG; Mfr_part_number: ERJ-2RKF6982X; Mistral Part No: 110009031082-R; Package: 0402; Part_type: RESISTORS\FIXED; Project: G4SLIM; RoHS: RoHS; Temperature: -55°C+155°C; Tolerance: 1%; Voltage: NA; Wattage: 1/10W; Weight: 0.8mg; Datasheet: Y:\MIS_DATABASE\DATASHEETS\RESISTORS\PAN-ERJSER_NOV17.PDF
R64 R110 = RESISTOR: RES 309K 1/10W 1% 0402; Chkd/date: JEBRAN/060215; Crtd /date: USMAN/140313; Custom_Duty: 15%; Customs_HS_Code: 85332119; Distributor_name: DIGIKEY; Distributor_part_number: P309KLCT-ND; Footprint Path: Y:\MIS_DATABASE\Library\ALTIUM_TOOL\PCB_FOOTPRINTS\Altium_Footprint_Lib.PcbLib; Height: 0.40MM; Library Path: Y:\MIS_DATABASE\Library\ALTIUM_TOOL\SCHEMATICS_PARTS\MS_DISCRETE_Library.schlib; Mfr_name: PANASONIC-ECG; Mfr_part_number: ERJ-2RKF3093X; Mistral Part No: 110013030008-R; Package: 0402; Part_type: RESISTORS\FIXED; Project: DTRM; RoHS: RoHS; Temperature: -55°C+155°C; Tolerance: 1%; Voltage: NA; Wattage: 1/10W; Weight: 0.8mg; Datasheet: Y:\MIS_DATABASE\DATASHEETS\RESISTORS\PAN-ERJSER_NOV17.PDF
R65 R111 = RESISTOR: RES 44.2K 1/16W 1% 0402; Chkd/date: ALVY/041120; Crtd /date: ALVY/041120; Custom_Duty: 15%; Customs_HS_Code: 85332119; Distributor_name: DIGIKEY; Distributor_part_number: 541-4106-1-ND; Footprint Path: Y:\MIS_DATABASE\Library\ALTIUM_TOOL\PCB_FOOTPRINTS\Altium_Footprint_Lib.PcbLib; Height: 0.35MM; Library Path: Y:\MIS_DATABASE\Library\ALTIUM_TOOL\SCHEMATICS_PARTS\MS_DISCRETE_Library.schlib; Mfr_name: VISHAY; Mfr_part_number: CRCW040244K2FKEDC; Mistral Part No: 110010070032-R; Package: 0402; Part_type: RESISTORS\FIXED; Project: TI_J7ES_EVM_FUSION2_SER_CAP; RoHS: RoHS; Temperature: -55°C+155°C; Tolerance: 1%; Voltage: NA; Wattage: 1/16W; Weight: 0.65mg; Datasheet: Y:\MIS_DATABASE\DATASHEETS\RESISTORS\CRCW_C-SER.PDF
R70 R116 = RESISTOR: RES 16.9K 1/10W 1% 0402; Chkd/date: SHREESHAIL/24050; Crtd /date: MAZHAR/260706; Custom_Duty: 15%; Customs_HS_Code: 85332119; Distributor_name: DIGIKEY; Distributor_part_number: P16.9KLCT-ND; Footprint Path: Y:\MIS_DATABASE\Library\ALTIUM_TOOL\PCB_FOOTPRINTS\Altium_Footprint_Lib.PcbLib; Height: 0.40MM; Library Path: Y:\MIS_DATABASE\Library\ALTIUM_TOOL\SCHEMATICS_PARTS\MS_DISCRETE_Library.schlib; Mfr_name: PANASONIC-ECG; Mfr_part_number: ERJ-2RKF1692X; Mistral Part No: 110009030351-R; Package: 0402; Part_type: RESISTORS\FIXED; Project: POWERBOX; RoHS: RoHS; Temperature: -55°C+155°C; Tolerance: 1%; Voltage: NA; Wattage: 1/10W; Weight: 0.8mg; Datasheet: Y:\MIS_DATABASE\DATASHEETS\RESISTORS\PAN-ERJSER_NOV17.PDF
R71 R118 = RESISTOR: RES 100K 1/16W 5% 0402; Chkd/date: VASANTHA/061216; Crtd /date: BAVISH/010611; Custom_Duty: 15%; Customs_HS_Code: 85332119; Distributor_name: DIGIKEY; Distributor_part_number: 541-100KJCT-ND; Footprint Path: Y:\MIS_DATABASE\Library\ALTIUM_TOOL\PCB_FOOTPRINTS\Altium_Footprint_Lib.PcbLib; Height: 0.40MM; Library Path: Y:\MIS_DATABASE\Library\ALTIUM_TOOL\SCHEMATICS_PARTS\MS_DISCRETE_Library.schlib; Mfr_name: VISHAY; Mfr_part_number: CRCW0402100KJNED; Mistral Part No: 110011060002-R; Package: 0402; Part_type: RESISTORS\FIXED; Project: AM4515_EVM_LCD; RoHS: RoHS; Temperature: -55°C+155°C; Tolerance: 5%; Voltage: NA; Wattage: 1/16W; Weight: 0.65mg; Datasheet: Y:\MIS_DATABASE\DATASHEETS\RESISTORS\CRCW0603.PDF
U1 U10 = TPD2E001DRLR_SOT-5: IC ESD-PROTECTION DIODE ARRAYS SOT-5; Chkd/date: NAVEED/150714; Crtd /date: MUDDU/250510; Custom_Duty: 15%; Customs_HS_Code: 85423100; Distributor_name: DIGIKEY; Distributor_part_number: 296-21883-1-ND; Footprint Path: Y:\MIS_DATABASE\Library\ALTIUM_TOOL\PCB_FOOTPRINTS\Altium_Footprint_Lib.PcbLib; Height: 0.60MM; Library Path: Y:\MIS_DATABASE\Library\ALTIUM_TOOL\SCHEMATICS_PARTS\MS_FILTER_Library.schlib; Mfr_name: TEXAS INSTRUMENTS; Mistral Part No: 140110060007-R; Package: SOT-5; Part_type: ICS\ANALOG\ACTIVE FILTER; Project: CENTAURUS; RoHS: RoHS; Temperature: -40°C+85°C; Tolerance: NA; Voltage: NA; Wattage: NA; Weight: 2.8mg; Datasheet: Y:\MIS_DATABASE\DATASHEETS\ICS\MISC\TPD2E001DRLR.PDF
U4 U13 = TPS25940_WQFN20_TI: IC eFUSE WITH TRUE REVERSE BLOCKING AND DEVSLEEP SUPPORT FOR SSD WQFN20; Chkd/date: MANIRAJA/220818; Crtd /date: ALVY/220818; Custom_Duty: 15%; Customs_HS_Code: 85423100; Distributor_name: DIGIKEY; Distributor_part_number: 296-46233-1-ND; Footprint Path: Y:\MIS_DATABASE\Library\ALTIUM_TOOL\PCB_FOOTPRINTS\Altium_Footprint_Lib.PcbLib; Height: 0.80MM; Library Path: Y:\MIS_DATABASE\Library\ALTIUM_TOOL\SCHEMATICS_PARTS\MS_MISCPOWER_Library.schlib; Library Ref: TPS25940_WQFN20; Mfr_name: TEXAS INSTRUMENTS; Mfr_part_number: TPS25940ARVCR; Mistral Part No: 142018080015-R; Package: WQFN20; Part_type: ICS\POWER\POWER MANAGEMENT; Project: TI_J7ES_EVM_FUSION2_SER_CAP; RoHS: RoHS; Temperature: -40°C+85°C; Tolerance: NA; Voltage: NA; Wattage: NA; Weight: 38.1mg; Datasheet: Y:\MIS_DATABASE\DATASHEETS\ICS\POWER\TPS25940XX.PDF
ACC1 ACC2 = ACCESSORY: STANDOFF BOARD TO BOARD 3.18MM LENGTH FEMALE/PRESS-IN TYPE #4-40 SS; Chkd/date: BAVISH/270611; Crtd /date: BAVISH/270611; Custom_Duty: NA; Customs_HS_Code: NA; Distributor_name: DIGIKEY; Distributor_part_number: SAM8861-ND; Footprint Path: NA; Height: 3.23MM; Library Path: NA; Mfr_name: SAMTEC; Mistral Part No: 160011060057-R; Package: SS; Part_type: MECHANICAL\STANDOFF; Project: GARUDA; RoHS: RoHS; Temperature: NA; Tolerance: NA; Voltage: NA; Wattage: NA; Weight: NA; Datasheet: Y:\MIS_DATABASE\DATASHEETS\MISC\MECHANICAL\SO-SERIES.PDF
FID1-FID6 = Fiducial
LBL1 LBL2 = ACCESSORY_THT-3-423-10: ACCESSORIE 1 WORKHORSE POLYSTER LABLE 0.25" X 1"; Chkd/date: MANIRAJA/270218; Crtd /date: ALVY/260218; Footprint Path: Y:\MIS_DATABASE\Library\ALTIUM_TOOL\PCB_FOOTPRINTS\Altium_Footprint_Lib.PcbLib; Library Path: Y:\MIS_DATABASE\Library\ALTIUM_TOOL\SCHEMATICS_PARTS\MS_MECHANICAL_Library.schlib; Mfr_name: BRADY; Mistral Part No: 160018020185; Part_type: ACCESSORIES; Project: TI_MAXIE_CPB
LOGO1 LOGO3 LOGO4 = TI_Logo
LOGO2 = FCC_disclaimer
MH1-MH4 = WASHER_FLAT: FLAT RETAINING WASHER FOR M3 NYLON; Chkd/date: MANIRAJA/160519; Crtd /date: ALVY/160519; Distributor_name: DIGIKEY; Distributor_part_number: RPC4978-ND; Mfr_name: ESSENTRA COMPONENTS; Mfr_part_number: RWM100A; Mistral Part No: 160019050020-R; Part_type: MECHANICAL\WASHERS; Project: J7ES_SOM_DUAL-LEO_PMIC; RoHS: RoHS; Datasheet: Y:\MIS_DATABASE\DATASHEETS\MISC\MECHANICAL\RWMXXXXA.PDF
PCB1 = ACCESSORY_PROC078: J7X FUSION2 SERIAL CAPTURE BOARD REV E3 BARE PCB; Mfr_name: ANY

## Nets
DGND: C5.2 C6.2 C7.2 C8.2 C21.2 C34.2 C36.2 C37.2 C40.2 C122.2 C135.2 C138.2 C139.2 C209.2 C212.2 C213.2 J3.SH1 J3.SH2 J3.SH3 J3.SH4 J4.2 J4.3 J4.4 J4.5 J9.SH1 J9.SH2 J9.SH3 J9.SH4 J10.2 J10.3 J10.4 J10.5 R2.1 R3.2 R19.1 R20.2 R21.2 R52.2 R62.2 R65.2 R70.2 R108.2 R111.2 R116.2 U1.4(GND) U4.1(DEVSLP) U4.3(PGTH) U4.16(GND) U4.21(EP) U10.4(GND) U13.1(DEVSLP) U13.3(PGTH) U13.16(GND) U13.21(EP) ; also on sheet 4 5 6 7 8 9 10 11 15 16
VCC_12V: C135.1 C209.1 R64.1 R110.1 U4.9(IN1) U4.10(IN2) U4.11(IN3) U4.12(IN4) U4.13(IN5) U13.9(IN1) U13.10(IN2) U13.11(IN3) U13.12(IN4) U13.13(IN5) ; also on sheet 8 9 11 15 16
CAM1_RIN_N: C132.1 R2.2
CAM1_RIN_P: C133.1 FL2.2 J4.1
CAM3_RIN_N: C198.1 R19.2
CAM3_RIN_P: C201.1 FL18.2 J10.1
HUB1_RIN0_N: C125.1 C132.2 ; also on sheet 4
HUB1_RIN0_P: C126.1 C133.2 ; also on sheet 4
HUB1_RIN2_N: C189.1 C198.2 ; also on sheet 4
HUB1_RIN2_P: C190.1 C201.2 ; also on sheet 4
RDR1_RIN_N: J3.4 L19.3(OUT1) U1.3(IO1)
RDR1_RIN_P: J3.2 L19.2(IN2) U1.2(NC) U1.5(IO2)
RDR3_RIN_N: J9.4 L22.3(OUT1) U10.2(NC) U10.5(IO2)
RDR3_RIN_P: J9.2 L22.2(IN2) U10.3(IO1)
T_RDR1_RIN_N: C125.2 L19.4(OUT2)
T_RDR1_RIN_P: C126.2 L19.1(IN1)
T_RDR3_RIN_N: C189.2 L22.4(OUT2)
T_RDR3_RIN_P: C190.2 L22.1(IN1)
V_RAD/CAM1: C6.1 C7.1 C122.1 C138.1 FL8.1 R4.1 R51.1 R71.1 U4.4(OUT1) U4.5(OUT2) U4.6(OUT3) U4.7(OUT4) U4.8(OUT5)
V_RAD/CAM1_CON1: C123.2 J3.1 L18.1 U1.1(VCC)
V_RAD/CAM1_CON3: C1.2 J3.3 L1.1
V_RAD/CAM3: C21.1 C36.1 C40.1 C212.1 FL24.1 R14.1 R23.1 R118.1 U13.4(OUT1) U13.5(OUT2) U13.6(OUT3) U13.7(OUT4) U13.8(OUT5)
V_RAD/CAM3_CON1: C27.2 J9.1 L8.1 U10.1(VCC)
V_RAD/CAM3_CON3: C25.2 J9.3 L7.1
N23276823: FL5.1 L3.2 R6.2
N23276832: C5.1 C8.1 FL8.2 L3.1 R6.1
N23276850: FL2.1 FL6.2
N23276958: FL5.2 FL6.1
N23280059: C1.1 R3.1
N23280068: C123.1 R52.1
N23280320: L1.2 R4.2
N23280326: L18.2 R51.2
N23296098: FL21.1 L10.2 R25.2
N23296110: C34.1 C37.1 FL24.2 L10.1 R25.1
N23296124: FL18.1 FL22.2
N23296133: FL21.2 FL22.1
N23296478: C27.1 R21.1
N23296488: C25.1 R20.1
N23296513: L7.2 R14.2
N23296515: L8.2 R23.2
N23311355: R71.2 U4.20(~{FLT})
N23312712: R63.1 R64.2 U4.14(EN/UVLO)
N23312989: R62.1 R63.2 U4.15(OVP)
N23313210: C139.1 U4.18(DVDT)
N23313421: R65.1 U4.17(ILIM)
N23314293: R70.1 U4.19(IMON)
N23316320: R109.1 R110.2 U13.14(EN/UVLO)
N23316340: R108.1 R109.2 U13.15(OVP)
N23316375: C213.1 U13.18(DVDT)
N23316392: R111.1 U13.17(ILIM)
N23316420: R116.1 U13.19(IMON)
N23316528: R118.2 U13.20(~{FLT})

Not connected (* = marked no-connect by the designer): U4 2(PGOOD)*; U13 2(PGOOD)

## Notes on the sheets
sheet 12
- HARDWARE SCHEMATICS
- ASSEMBLY NOTES
- SUPPORT FOR CSI-TX CABLE
- FIDUCIALS
- 1. All MSL components should be baked as per JEDEC standard.
  2. PCB should be baked at 120 degree for 8 hours.
  3. Board assembly must comply with workmanship standards.
  IPC-A-610 Class 2, unless otherwise specified.
  4. These assemblies are ESD sensitive, ESD precautions
  shall be observed.
  5. These assemblies must be clean and free from flux and
  all contaminants. Use of no clean flux is not acceptable.
  6. Provide serial numbers to the assembled boards for identification.
  7. The assembled board are wrapped in ESD Covers(individual) and
  packed securely before shipment.
- Should be placed with CSI-TX
  connector, in the same side
- WASHERS
- LABELS
- Board Serial No.
- Assembly Revision.
- BARE PCB
- LOGOs
- Texas Intruments
- For Evaluation only; not FCC approved for resale
- WEEE Mark
- CE Mark
sheet 13
- FPD Link Camera/RADAR Input1
- Power Over Coax
- FPD LINK Camera Input
- Place with minimum stub length
- Silkscreen for J2:
  "CAMERA IN 1"
- 100E
- RADAR Input1
- eFUSE
- PCB Note:  Route signals as 100-ohm differential
- Silkscreen for J3:
  "RADAR IN1"
- Current limit
  set to 2A
- PCB Note:  Place U20 HSD Connector J3
sheet 14
- FPD Link Camera/RADAR Input3
- Power Over Coax
- FPD LINK Camera Input
- Silkscreen for J6:
  "CAMERA CONN 3"
- Place with minimum stub length
- 100E
- RADAR Input3
- PCB Note:  Route signals as 100-ohm differential
- Silkscreen for J7:
  "RADAR IN3"
- eFUSE
- PCB Note:  Place near HSD Connector J7
- Current limit
  set to 2A
